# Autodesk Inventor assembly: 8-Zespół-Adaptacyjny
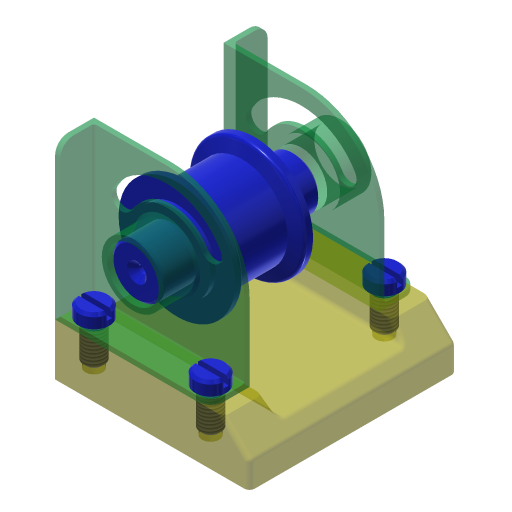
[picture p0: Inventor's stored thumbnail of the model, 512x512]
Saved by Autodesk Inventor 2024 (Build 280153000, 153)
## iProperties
Created: 2023-03
Part Number: 8-Zespół-Adaptacyjny
Document SubType Name: Assembly
Designer: Andrzej Jaskulski
Checked By: A.J.
Engr Approved By: Andrzej Jaskulski
Mfg Approved By: Andrzej Jaskulski
Authority: A.J.
Company: ATC
Control State: 0
Master: False
Checked Out: False
Shininess: 20.0
Length Units: 11269
Angle Units: 11279
Time Units: 11290
Mass Units: 11283
Length Display Precision: 3
Angle Display Precision: 2
Compacted: True
Density: 0.0
Volumn: 0.0
Area: 0.0
PropertySet Name: Model Information
Title: A.J.: Kurs R2024-MEP
Author: Andrzej Jaskulski
Revision Number: 1/24
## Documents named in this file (6)
- C:\Users\AndJas\Documents\R2024-MEP\Obszar roboczy\8-Zespół-Adaptacyjny.iam
- C:\Users\AndJas\Documents\R2024-MEP\Obszar roboczy\P.ipt
- C:\Users\AndJas\Documents\R2024-MEP\Obszar roboczy\WP.ipt
- C:\Users\AndJas\Documents\R2024-MEP\Obszar roboczy\WL.ipt
- C:\Users\AndJas\Documents\R2024-MEP\Obszar roboczy\W.ipt
- C:\Users\AndJas\Documents\R2024-MEP\Obszar roboczy\Rolka-Toczona.ipt
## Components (8 placed, 5 different names)
1. P:1 — Zestawiające:1, Zestawiające:2, Zestawiające:3, Zestawiające:4
2. WP:1 — Zestawiające:1, Zestawiające:2, Wstawiające:1, Wstawiające:2, Wstawiające:5
3. WL:1 — Zestawiające:3, Zestawiające:4, Wstawiające:3, Wstawiające:4
4. W:1 — Wstawiające:1
5. W:2 — Wstawiające:4
6. W:3 — Wstawiające:3
7. W:4 — Wstawiające:2
8. Rolka-Toczona:1 — Wstawiające:5
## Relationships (9: Insert 5, Mate 4)
- Zestawiające:1 [Mate]: P:1 ↔ WP:1
- Zestawiające:2 [Mate]: P:1 ↔ WP:1
- Zestawiające:3 [Mate]: P:1 ↔ WL:1
- Zestawiające:4 [Mate]: P:1 ↔ WL:1
- Wstawiające:1 [Insert]: WP:1 ↔ W:1
- Wstawiające:2 [Insert]: WP:1 ↔ W:4
- Wstawiające:3 [Insert]: WL:1 ↔ W:3
- Wstawiające:4 [Insert]: WL:1 ↔ W:2
- Wstawiające:5 [Insert]: WP:1 ↔ Rolka-Toczona:1
